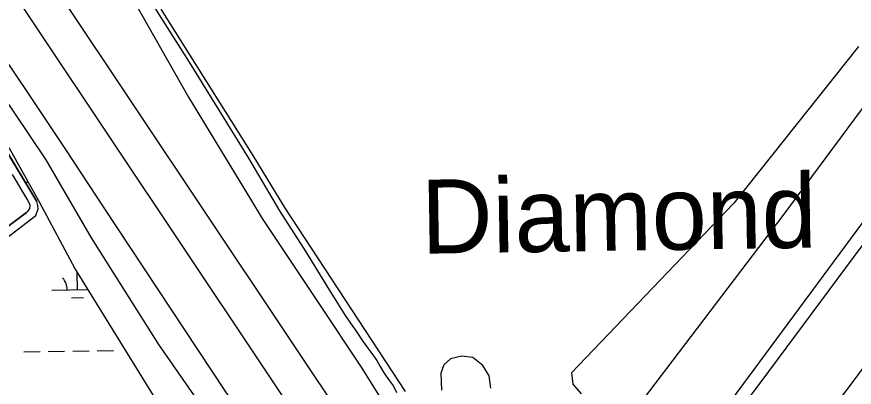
# Model space of a CAD drawing. Extents: x 3767014 to 3805179, y 361544 to 387384.
# Drawn here: x 3775133 to 3776776, y 382025 to 382751 of the extents above; entities that cross this region are included whole.
import ezdxf

# ---------------------------------------------------------------- set-up
doc = ezdxf.new("R2010")
doc.units = 0
for name, color, linetype in [('V-LEVE-TOET', 7, 'Continuous'), ('V-RIVR-EDGE', 7, 'Continuous'), ('V-ROAD-CNTR', 7, 'Continuous'), ('V-SITE-VEGE', 7, 'Continuous'), ('V-TOPO-GNAM-IDEN', 7, 'Continuous'), ('V-TOPO-SHOR', 7, 'Continuous'), ('V-WETL-SWMP', 7, 'Continuous')]:
    doc.layers.add(name, color=color, linetype=linetype)

msp = doc.modelspace()

# ---------------------------------------------------------------- linework, layer by layer
at = {"layer": 'V-LEVE-TOET'}
for points in [[(3775056.629, 382746.75), (3775228.473, 382491.022), (3775303.487, 382376.758), (3775540.799, 382017.645), (3775737.184, 381730.635), (3775757.615, 381721.132), (3775788.935, 381714.361), (3775794.388, 381707.562), (3775798.478, 381702.12), (3775794.403, 381695.309), (3775790.338, 381680.33), (3775793.07, 381672.164), (3775802.626, 381650.394)], [(3776472.401, 380540.333), (3776353.761, 380706.274), (3776224.202, 380895.348), (3776111.009, 381059.935), (3776004.618, 381228.617), (3775832.766, 381493.874), (3775730.47, 381651.668), (3775725.023, 381654.383), (3775704.594, 381661.166), (3775693.696, 381666.6), (3775684.149, 381681.562), (3775674.583, 381711.5), (3775665.022, 381737.354), (3775656.83, 381756.405), (3775644.551, 381779.533), (3775517.728, 381956.357), (3775411.357, 382108.699), (3775279.052, 382318.189), (3775190.38, 382470.554), (3775033.54, 382703.158)]]:
    msp.add_lwpolyline(points, dxfattribs=at)
at = {"layer": 'V-RIVR-EDGE'}
msp.add_spline([(3776564.722, 385223.299), (3776600.731, 385181.098), (3776661.2, 385105.736), (3776715.203, 385032.007), (3776816.784, 384902.358), (3776846.605, 384861.038), (3776857.883, 384843.218), (3776882.888, 384816.468), (3776915.962, 384782.419), (3776954.66, 384732.99), (3776978.836, 384698.155), (3777017.529, 384647.108), (3777120.713, 384511.794), (3777150.55, 384476.944), (3777181.198, 384442.901), (3777207.8, 384408.06), (3777254.587, 384359.42), (3777285.235, 384325.377), (3777306.975, 384286.503), (3777352.136, 384234.632), (3777398.919, 384184.375), (3777453.759, 384121.966), (3777499.732, 384071.711), (3777554.576, 384010.92), (3777589.252, 383970.397), (3777621.507, 383932.306), (3777678.778, 383871.509), (3777722.335, 383825.304), (3777756.204, 383785.592), (3777794.915, 383741.824), (3777871.521, 383651.056), (3777927.937, 383571.66), (3777966.622, 383517.378), (3777996.431, 383471.207), (3778029.475, 383425.027), (3778067.358, 383373.174), (3778126.177, 383284.876), (3778156.015, 383250.026), (3778180.211, 383223.278), (3778202.787, 383195.725), (3778212.458, 383181.952), (3778217.257, 383160.105), (3778222.842, 383129.359), (3778231.692, 383110.736), (3778252.643, 383079.952), (3778272.805, 383057.257), (3778301.832, 383021.601), (3778314.725, 383002.968), (3778332.478, 382986.749), (3778341.366, 382983.492), (3778349.453, 382983.472), (3778360.791, 382989.914), (3778364.028, 382990.715), (3778372.922, 382989.884), (3778380.996, 382984.203), (3778411.652, 382953.395), (3778438.266, 382923.406), (3778460.048, 382901.516), (3778499.574, 382860.173), (3778541.506, 382810.736), (3778575.377, 382771.833), (3778604.389, 382730.515), (3778631.764, 382681.114), (3778646.24, 382647.92)], degree=3, dxfattribs=at)
at = {"layer": 'V-ROAD-CNTR'}
for points in [[(3773625.9, 385186.349), (3774181.119, 384346.19), (3775216.704, 382795.428), (3776380.625, 381052.708), (3777283.017, 379696.102), (3777445.775, 379463.11), (3777569.907, 379293.951), (3777617.356, 379230.723), (3777830.706, 378985.678), (3778010.091, 378796.753), (3778274.944, 378542.232), (3778638.611, 378241.543), (3779057.65, 377959.067)], [(3773538.269, 385185.098), (3774135.962, 384280.668), (3775171.547, 382729.907), (3776335.468, 380987.186), (3777237.86, 379630.58), (3777400.618, 379397.588), (3777524.75, 379228.43), (3777572.199, 379165.201), (3777785.549, 378920.156), (3777964.934, 378731.232), (3778229.788, 378476.71), (3778593.454, 378176.022), (3779012.493, 377893.545)]]:
    msp.add_lwpolyline(points, dxfattribs=at)
at = {"layer": 'V-SITE-VEGE'}
msp.add_lwpolyline([(3776803.514, 382363.024), (3776332.236, 381726.684), (3776218.705, 381577.162), (3776211.062, 381576.197), (3776197.996, 381582.232), (3776183.322, 381598.778), (3776173.43, 381614.054), (3776162.895, 381632.834), (3776155.236, 381647.158), (3776131.938, 381683.76), (3776131.928, 381692.042), (3776325.273, 381952.826), (3776636.608, 382361.865), (3776945.844, 382778.494), (3777206.882, 383132.355), (3777295.325, 383013.713)], close=True, dxfattribs=at)
for points in [[(3775895.189, 382016.791), (3775658.77, 382377.442), (3775596.29, 382479.451), (3775416.309, 382766.32)], [(3776784.093, 382693.291), (3776539.633, 382385.861)], [(3776539.633, 382385.861), (3776221.267, 382053.166), (3776223.614, 382030.73), (3776240.273, 382011.796)], [(3776884.633, 382184.432), (3776687.468, 381921.574), (3776421.14, 381565.941), (3776308.86, 381433.937), (3776300.421, 381431.856), (3776293.257, 381432.165), (3776282.578, 381437.568), (3776267.268, 381455.545), (3776236.642, 381495.006), (3776227.069, 381508.529), (3776220.366, 381520.944), (3776218.281, 381532.726), (3776224.473, 381548.662), (3776339.275, 381699.62), (3776591.622, 382033.098), (3776844.748, 382373.426)], [(3776062.695, 382023.185), (3776059.568, 382047.552), (3776047.163, 382067.653), (3776027.801, 382083.106), (3776006.135, 382085.786), (3775984.091, 382080.345), (3775970.566, 382068.725), (3775964.78, 382052.468), (3775965.982, 382019.2)]]:
    msp.add_lwpolyline(points, dxfattribs=at)
at = {"layer": 'V-TOPO-SHOR'}
for points in [[(3774828.775, 382935.95), (3774846.05, 382897.624), (3774859.608, 382872.397), (3774893.809, 382817.668), (3774965.694, 382710.021), (3775086.075, 382531.204), (3775172.206, 382389.015)], [(3775384.563, 382798.775), (3775362.51, 382782.575), (3775469.418, 382593.453), (3775591.178, 382393.408), (3775614.273, 382355.813)], [(3775384.563, 382798.775), (3775470.682, 382662.165), (3775587.559, 382473.786), (3775648.485, 382370.829)], [(3775123.939, 382442.181), (3775153.686, 382391.768), (3775158.21, 382383.068), (3775158.251, 382380.436), (3775157.458, 382375.159), (3775153.248, 382368.763)], [(3774999.22, 382231.223), (3775133.55, 382333.574), (3775170.088, 382361.584), (3775174.914, 382375.036), (3775173.828, 382381.489), (3775172.206, 382389.015)], [(3774636.357, 382201.23), (3774722.041, 382263.364), (3774782.222, 382309.69), (3774789.746, 382314.003), (3774795.661, 382315.623), (3774801.577, 382314.018), (3774808.58, 382305.42), (3774888.851, 382194.187), (3774899.083, 382183.443), (3774900.695, 382183.445), (3774901.77, 382183.986), (3774907.684, 382186.145), (3774963.568, 382226.548), (3775151.636, 382367.685), (3775153.248, 382368.763)], [(3775648.485, 382370.829), (3775699.732, 382290.183), (3775751.176, 382207.395), (3775778.65, 382163.67), (3775800.082, 382132.772), (3775810.797, 382116.06), (3775821.318, 382101.876), (3775829.694, 382091.187), (3775839.434, 382077.586), (3775845.867, 382065.73), (3775852.298, 382054.458), (3775857.559, 382046.491), (3775863.791, 382037.552), (3775871.778, 382027.06), (3775878.019, 382014.621)], [(3775614.273, 382355.813), (3775725.137, 382189.276), (3775808.72, 382064.518), (3775845.941, 382004.663)]]:
    msp.add_lwpolyline(points, dxfattribs=at)
at = {"layer": 'V-WETL-SWMP'}
for p, q in [((3775172.207, 382389.016), (3775086.076, 382531.203)), ((3775116.984, 382495.024), (3775175.932, 382389.569)), ((3775149.035, 382427.269), (3775154.814, 382427.349)), ((3775173.829, 382381.488), (3775172.207, 382389.016)), ((3775174.913, 382375.035), (3775173.829, 382381.488)), ((3775175.932, 382389.569), (3775247.308, 382256.515)), ((3775133.551, 382333.573), (3775170.089, 382361.584)), ((3775170.089, 382361.584), (3775174.913, 382375.035)), ((3774999.219, 382231.224), (3775133.551, 382333.573)), ((3775247.308, 382256.515), (3775448.575, 381930.487)), ((3775251.625, 382216.07), (3775251.15, 382250.292)), ((3775201.63, 382215.375), (3775272.101, 382216.354)), ((3775239.841, 382200.473), (3775263.839, 382200.807)), ((3775290.446, 382096.526), (3775322.442, 382096.971)), ((3775146.459, 382094.526), (3775178.456, 382094.971)), ((3775194.455, 382095.193), (3775226.452, 382095.637)), ((3775242.45, 382095.859), (3775274.447, 382096.304))]:
    msp.add_line(p, q, dxfattribs=at)
msp.add_lwpolyline([(3775123.939, 382442.181), (3775153.687, 382391.768), (3775158.211, 382383.067), (3775158.252, 382380.436), (3775157.458, 382375.159), (3775153.247, 382368.763), (3775151.635, 382367.686), (3774963.568, 382226.548)], dxfattribs=at)
for centre, start, end in [((3775196.381, 382215.777), 0.024037, 41.567696), ((3775306.856, 382217.312), 180.264917, 181.567693)]:
    msp.add_arc(centre, 35.246, start, end, dxfattribs=at)

# ---------------------------------------------------------------- texts
at = {"layer": 'V-TOPO-GNAM-IDEN'}
msp.add_text('Diamond', height=145, rotation=0.907408, dxfattribs=at).set_placement((3775927.237, 382286.645))

doc.saveas('drawing.dxf')
